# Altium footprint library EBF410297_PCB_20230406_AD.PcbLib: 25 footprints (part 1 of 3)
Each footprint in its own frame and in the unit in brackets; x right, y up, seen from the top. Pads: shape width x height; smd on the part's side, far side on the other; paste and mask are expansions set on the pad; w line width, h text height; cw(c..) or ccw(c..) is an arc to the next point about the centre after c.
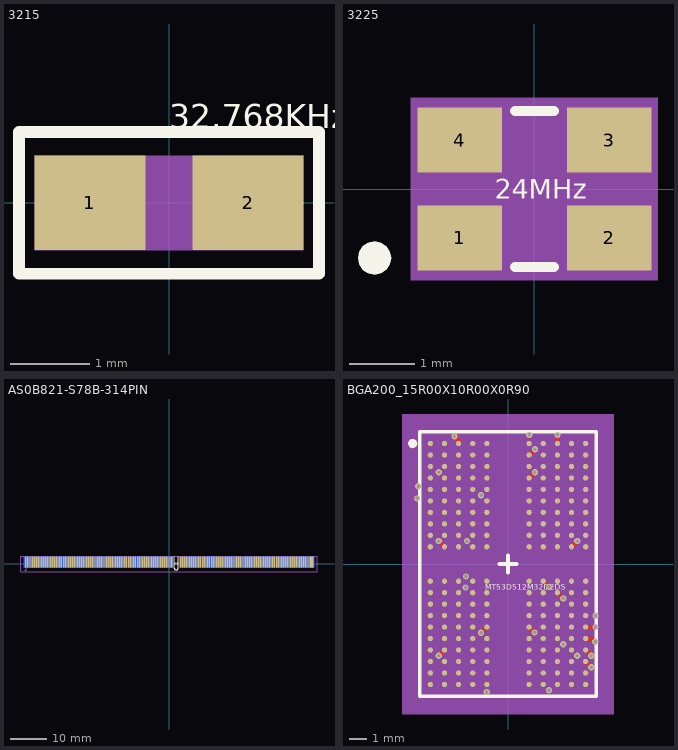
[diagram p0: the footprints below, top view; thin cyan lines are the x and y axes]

## 3215 [mm] "3215"
pads (2):
  rect 1.4x1.2 smd: 1(-1.001,0) 2(1.001,0)
Top Overlay:
  lines w0.15: -1.9,-0.899 1.9,-0.899 1.9,0.899 -1.9,0.899 -1.9,-0.899
  text "32.768KHz" at 0,0.945 h0.3
Top 3D Body:
  region: -1.699,-0.599 1.699,-0.599 1.699,0.599 -1.699,0.599
Mechanical 14:
  text "2" at 1.001,0.152 h0.38
  text "1" at -1.001,0.152 h0.38
3D body: height 3.81, standoff 0, extent -1.699,-0.599 1.699,0.599

## 3225 [mm] "3225"
pads (4):
  rect 1.3x1 smd: 1(-1.15,-0.75) 2(1.15,-0.75) 3(1.15,0.75) 4(-1.15,0.75)
Top Overlay:
  dashed: -2.201,-1.06 -2.221,-0.962 -2.276,-0.879 -2.359,-0.824 -2.456,-0.805 -2.554,-0.824 -2.581,-0.843 -2.636,-0.879 -2.692,-0.962 -2.711,-1.06 -2.692,-1.157 -2.636,-1.24 -2.581,-1.277 -2.554,-1.295 -2.456,-1.315 -2.359,-1.295 -2.276,-1.24 -2.221,-1.157
  lines w0.15: -0.3,-1.2 0.3,-1.2 ; -0.3,1.2 0.3,1.2
  text "24MHz" at -0.61,-0.152 h0.3
Top 3D Body:
  region: -1.9,1.4 -1.9,-1.4 1.9,-1.4 1.9,1.4
Mechanical 14:
  text "3" at 0.785,0.75 h0.91
  text "1" at -1.516,-0.75 h0.91
  text "4" at -1.516,0.75 h0.91
  text "2" at 0.785,-0.75 h0.91
Top Assembly:
  lines w0.15: -1.6,-1.25 -1.6,1.25 1.6,1.25 1.6,-1.25 -1.6,-1.25
3D body: height 3.81, standoff 0, extent -1.9,-1.4 1.9,1.4

## AS0B821-S78B-314PIN [mm] "AS0B821-S78B-314PIN"
pads (314):
  rect 0.35x3.1 smd far side: 1(-40,0.525) 3(-39.5,0.525) 5(-39,0.525) 7(-38.5,0.525) 9(-38,0.525) 11(-37.5,0.525) 13(-37,0.525) 15(-36.5,0.525) 17(-36,0.525) 19(-35.5,0.525) 21(-35,0.525) 23(-34.5,0.525) 25(-34,0.525) 27(-33.5,0.525) 29(-33,0.525) 31(-32.5,0.525) 33(-32,0.525) 35(-31.5,0.525) 37(-31,0.525) 39(-30.5,0.525) 41(-30,0.525) 43(-29.5,0.525) 45(-29,0.525) 47(-28.5,0.525) 49(-28,0.525) 51(-27.5,0.525) 53(-27,0.525) 55(-26.5,0.525) 57(-26,0.525) 59(-25.5,0.525) 61(-25,0.525) 63(-24.5,0.525) 65(-24,0.525) 67(-23.5,0.525) 69(-23,0.525) 71(-22.5,0.525) 73(-22,0.525) 75(-21.5,0.525) 77(-21,0.525) 79(-20.5,0.525) 81(-20,0.525) 83(-19.5,0.525) 85(-19,0.525) 87(-18.5,0.525) 89(-18,0.525) 91(-17.5,0.525) 93(-17,0.525) 95(-16.5,0.525) 97(-16,0.525) 99(-15.5,0.525) 101(-15,0.525) 103(-14.5,0.525) 105(-14,0.525) 107(-13.5,0.525) 109(-13,0.525) 111(-12.5,0.525) 113(-12,0.525) 115(-11.5,0.525) 117(-11,0.525) 119(-10.5,0.525) 121(-10,0.525) 123(-9.5,0.525) 125(-9,0.525) 127(-8.5,0.525) 129(-8,0.525) 131(-7.5,0.525) 133(-7,0.525) 135(-6.5,0.525) 137(-6,0.525) 139(-5.5,0.525) 141(-5,0.525) 143(-4.5,0.525) 145(-4,0.525) 147(-3.5,0.525) 149(-3,0.525) 151(-2.5,0.525) 153(-2,0.525) 155(-1.5,0.525) 157(-1,0.525) 159(-0.5,0.525) 161(0,0.525) 163(0.5,0.525) 165(1,0.525) 167(3,0.525) 169(3.5,0.525) 171(4,0.525) 173(4.5,0.525) 175(5,0.525) 177(5.5,0.525) 179(6,0.525) 181(6.5,0.525) 183(7,0.525) 185(7.5,0.525) 187(8,0.525) 189(8.5,0.525) 191(9,0.525) 193(9.5,0.525) 195(10,0.525) 197(10.5,0.525) 199(11,0.525) 201(11.5,0.525) 203(12,0.525) 205(12.5,0.525) 207(13,0.525) 209(13.5,0.525) 211(14,0.525) 213(14.5,0.525) 215(15,0.525) 217(15.5,0.525) 219(16,0.525) 221(16.5,0.525) 223(17,0.525) 225(17.5,0.525) 227(18,0.525) 229(18.5,0.525) 231(19,0.525) 233(19.5,0.525) 235(20,0.525) 237(20.5,0.525) 239(21,0.525) 241(21.5,0.525) 243(22,0.525) 245(22.5,0.525) 247(23,0.525) 249(23.5,0.525) 251(24,0.525) 253(24.5,0.525) 255(25,0.525) 257(25.5,0.525) 259(26,0.525) 261(26.5,0.525) 263(27,0.525) 265(27.5,0.525) 267(28,0.525) 269(28.5,0.525) 271(29,0.525) 273(29.5,0.525) 275(30,0.525) 277(30.5,0.525) 279(31,0.525) 281(31.5,0.525) 283(32,0.525) 285(32.5,0.525) 287(33,0.525) 289(33.5,0.525) 291(34,0.525) 293(34.5,0.525) 295(35,0.525) 297(35.5,0.525) 299(36,0.525) 301(36.5,0.525) 303(37,0.525) 305(37.5,0.525) 307(38,0.525) 309(38.5,0.525) 311(39,0.525) 313(39.5,0.525) 314(40,0.525)
  rect 0.35x3.1 smd: 2(-39.75,0.525) 4(-39.25,0.525) 6(-38.75,0.525) 8(-38.25,0.525) 10(-37.75,0.525) 12(-37.25,0.525) 14(-36.75,0.525) 16(-36.25,0.525) 18(-35.75,0.525) 20(-35.25,0.525) 22(-34.75,0.525) 24(-34.25,0.525) 26(-33.75,0.525) 28(-33.25,0.525) 30(-32.75,0.525) 32(-32.25,0.525) 34(-31.75,0.525) 36(-31.25,0.525) 38(-30.75,0.525) 40(-30.25,0.525) 42(-29.75,0.525) 44(-29.25,0.525) 46(-28.75,0.525) 48(-28.25,0.525) 50(-27.75,0.525) 52(-27.25,0.525) 54(-26.75,0.525) 56(-26.25,0.525) 58(-25.75,0.525) 60(-25.25,0.525) 62(-24.75,0.525) 64(-24.25,0.525) 66(-23.75,0.525) 68(-23.25,0.525) 70(-22.75,0.525) 72(-22.25,0.525) 74(-21.75,0.525) 76(-21.25,0.525) 78(-20.75,0.525) 80(-20.25,0.525) 82(-19.75,0.525) 84(-19.25,0.525) 86(-18.75,0.525) 88(-18.25,0.525) 90(-17.75,0.525) 92(-17.25,0.525) 94(-16.75,0.525) 96(-16.25,0.525) 98(-15.75,0.525) 100(-15.25,0.525) 102(-14.75,0.525) 104(-14.25,0.525) 106(-13.75,0.525) 108(-13.25,0.525) 110(-12.75,0.525) 112(-12.25,0.525) 114(-11.75,0.525) 116(-11.25,0.525) 118(-10.75,0.525) 120(-10.25,0.525) 122(-9.75,0.525) 124(-9.25,0.525) 126(-8.75,0.525) 128(-8.25,0.525) 130(-7.75,0.525) 132(-7.25,0.525) 134(-6.75,0.525) 136(-6.25,0.525) 138(-5.75,0.525) 140(-5.25,0.525) 142(-4.75,0.525) 144(-4.25,0.525) 146(-3.75,0.525) 148(-3.25,0.525) 150(-2.75,0.525) 152(-2.25,0.525) 154(-1.75,0.525) 156(-1.25,0.525) 158(-0.75,0.525) 160(-0.25,0.525) 162(0.25,0.525) 164(0.75,0.525) 166(3.25,0.525) 168(3.75,0.525) 170(4.25,0.525) 172(4.75,0.525) 174(5.25,0.525) 176(5.75,0.525) 178(6.25,0.525) 180(6.75,0.525) 182(7.25,0.525) 184(7.75,0.525) 186(8.25,0.525) 188(8.75,0.525) 190(9.25,0.525) 192(9.75,0.525) 194(10.25,0.525) 196(10.75,0.525) 198(11.25,0.525) 200(11.75,0.525) 202(12.25,0.525) 204(12.75,0.525) 206(13.25,0.525) 208(13.75,0.525) 210(14.25,0.525) 212(14.75,0.525) 214(15.25,0.525) 216(15.75,0.525) 218(16.25,0.525) 220(16.75,0.525) 222(17.25,0.525) 224(17.75,0.525) 226(18.25,0.525) 228(18.75,0.525) 230(19.25,0.525) 232(19.75,0.525) 234(20.25,0.525) 236(20.75,0.525) 238(21.25,0.525) 240(21.75,0.525) 242(22.25,0.525) 244(22.75,0.525) 246(23.25,0.525) 248(23.75,0.525) 250(24.25,0.525) 252(24.75,0.525) 254(25.25,0.525) 256(25.75,0.525) 258(26.25,0.525) 260(26.75,0.525) 262(27.25,0.525) 264(27.75,0.525) 266(28.25,0.525) 268(28.75,0.525) 270(29.25,0.525) 272(29.75,0.525) 274(30.25,0.525) 276(30.75,0.525) 278(31.25,0.525) 280(31.75,0.525) 282(32.25,0.525) 284(32.75,0.525) 286(33.25,0.525) 288(33.75,0.525) 290(34.25,0.525) 292(34.75,0.525) 294(35.25,0.525) 296(35.75,0.525) 298(36.25,0.525) 300(36.75,0.525) 302(37.25,0.525) 304(37.75,0.525) 306(38.25,0.525) 308(38.75,0.525) 310(39.25,0.525)
  rect 0.425x3.1 smd: 312(39.75,0.525)
Top Overlay:
  lines w0.15: 1.5,2.075 1.5,-1.175 ccw(c2,-1.175) 2.5,-1.175 2.5,2.075
  text "2" at -40,-1.875 h0.76
  text "AS0B821-S55B-314PIN" at -2.316,-0.152 h0.3
Bottom Overlay:
  text "1" at -39.686,-1.915 h0.76
Top 3D Body:
  lines w0.025: -41.075,-2.15 -41.075,2.15 41.075,2.15 41.075,-2.15 -41.075,-2.15
Mechanical 14:
  text "102" at -15.512,0.525 h0.64
  text "104" at -15.012,0.525 h0.64
  text "193" at 8.738,0.525 h0.64
  text "191" at 8.238,0.525 h0.64
  text "232" at 18.988,0.525 h0.64
  text "161" at -0.762,0.525 h0.64
  text "230" at 18.488,0.525 h0.64
  text "163" at -0.262,0.525 h0.64
  text "236" at 19.988,0.525 h0.64
  text "234" at 19.488,0.525 h0.64
  text "118" at -11.512,0.525 h0.64
  text "165" at 0.238,0.525 h0.64
  text "252" at 23.988,0.525 h0.64
  text "71" at -23.008,0.525 h0.64
  text "250" at 23.488,0.525 h0.64
  text "73" at -22.508,0.525 h0.64
  text "256" at 24.988,0.525 h0.64
  text "69" at -23.508,0.525 h0.64
  text "120" at -11.012,0.525 h0.64
  text "254" at 24.488,0.525 h0.64
  text "61" at -25.508,0.525 h0.64
  text "242" at 21.488,0.525 h0.64
  text "240" at 20.988,0.525 h0.64
  text "124" at -10.012,0.525 h0.64
  text "246" at 22.488,0.525 h0.64
  text "126" at -9.512,0.525 h0.64
  text "244" at 21.988,0.525 h0.64
  text "63" at -25.008,0.525 h0.64
  text "305" at 36.738,0.525 h0.64
  text "307" at 37.238,0.525 h0.64
  text "303" at 36.238,0.525 h0.64
  text "65" at -24.508,0.525 h0.64
  text "301" at 35.738,0.525 h0.64
  text "29" at -33.508,0.525 h0.64
  text "66" at -24.258,0.525 h0.64
  text "64" at -24.758,0.525 h0.64
  text "199" at 10.238,0.525 h0.64
  text "197" at 9.738,0.525 h0.64
  text "267" at 27.238,0.525 h0.64
  text "203" at 11.238,0.525 h0.64
  text "265" at 26.738,0.525 h0.64
  text "201" at 10.738,0.525 h0.64
  text "313" at 38.738,0.525 h0.64
  text "215" at 14.238,0.525 h0.64
  text "213" at 13.738,0.525 h0.64
  text "219" at 15.238,0.525 h0.64
  text "314" at 39.238,0.525 h0.64
  text "217" at 14.738,0.525 h0.64
  text "209" at 12.738,0.525 h0.64
  text "6" at -39.004,0.525 h0.64
  text "2" at -40.004,0.525 h0.64
  text "4" at -39.504,0.525 h0.64
  text "5" at -39.254,0.525 h0.64
  text "3" at -39.754,0.525 h0.64
  text "1" at -40.254,0.525 h0.64
  text "207" at 12.238,0.525 h0.64
  text "269" at 27.738,0.525 h0.64
  text "266" at 27.488,0.525 h0.64
  text "114" at -12.512,0.525 h0.64
  text "270" at 28.488,0.525 h0.64
  text "59" at -26.008,0.525 h0.64
  text "112" at -13.012,0.525 h0.64
  text "271" at 28.238,0.525 h0.64
  text "262" at 26.488,0.525 h0.64
  text "57" at -26.508,0.525 h0.64
  text "110" at -13.512,0.525 h0.64
  text "264" at 26.988,0.525 h0.64
  text "55" at -27.008,0.525 h0.64
  text "108" at -14.012,0.525 h0.64
  text "268" at 27.988,0.525 h0.64
  text "75" at -22.008,0.525 h0.64
  text "129" at -8.762,0.525 h0.64
  text "260" at 25.988,0.525 h0.64
  text "79" at -21.008,0.525 h0.64
  text "136" at -7.012,0.525 h0.64
  text "77" at -21.508,0.525 h0.64
  text "134" at -7.512,0.525 h0.64
  text "132" at -8.012,0.525 h0.64
  text "130" at -8.512,0.525 h0.64
  text "89" at -18.508,0.525 h0.64
  text "83" at -20.008,0.525 h0.64
  text "142" at -5.512,0.525 h0.64
  text "140" at -6.012,0.525 h0.64
  text "85" at -19.508,0.525 h0.64
  text "70" at -23.258,0.525 h0.64
  text "68" at -23.758,0.525 h0.64
  text "275" at 29.238,0.525 h0.64
  text "273" at 28.738,0.525 h0.64
  text "284" at 31.988,0.525 h0.64
  text "282" at 31.488,0.525 h0.64
  text "277" at 29.738,0.525 h0.64
  text "274" at 29.488,0.525 h0.64
  text "279" at 30.238,0.525 h0.64
  text "178" at 5.488,0.525 h0.64
  text "287" at 32.238,0.525 h0.64
  text "291" at 33.238,0.525 h0.64
  text "289" at 32.738,0.525 h0.64
  text "180" at 5.988,0.525 h0.64
  text "182" at 6.488,0.525 h0.64
  text "74" at -22.258,0.525 h0.64
  text "76" at -21.758,0.525 h0.64
  text "78" at -21.258,0.525 h0.64
  text "302" at 36.488,0.525 h0.64
  text "80" at -20.758,0.525 h0.64
  text "304" at 36.988,0.525 h0.64
  text "99" at -16.008,0.525 h0.64
  text "82" at -20.258,0.525 h0.64
  text "105" at -14.762,0.525 h0.64
  text "84" at -19.758,0.525 h0.64
  text "93" at -17.508,0.525 h0.64
  text "86" at -19.258,0.525 h0.64
  text "296" at 34.988,0.525 h0.64
  text "103" at -15.262,0.525 h0.64
  text "88" at -18.758,0.525 h0.64
  text "298" at 35.488,0.525 h0.64
  text "97" at -16.508,0.525 h0.64
  text "35" at -32.008,0.525 h0.64
  text "95" at -17.008,0.525 h0.64
  text "37" at -31.508,0.525 h0.64
  text "13" at -37.508,0.525 h0.64
  text "15" at -37.008,0.525 h0.64
  text "92" at -17.758,0.525 h0.64
  text "94" at -17.258,0.525 h0.64
  text "276" at 29.988,0.525 h0.64
  text "278" at 30.488,0.525 h0.64
  text "280" at 30.988,0.525 h0.64
  text "293" at 33.738,0.525 h0.64
  text "297" at 34.738,0.525 h0.64
  text "295" at 34.238,0.525 h0.64
  text "308" at 37.988,0.525 h0.64
  text "115" at -12.262,0.525 h0.64
  text "113" at -12.762,0.525 h0.64
  text "310" at 38.488,0.525 h0.64
  text "36" at -31.758,0.525 h0.64
  text "34" at -32.258,0.525 h0.64
  text "292" at 33.988,0.525 h0.64
  text "290" at 33.488,0.525 h0.64
  text "211" at 13.238,0.525 h0.64
  text "249" at 22.738,0.525 h0.64
  text "311" at 38.238,0.525 h0.64
  text "294" at 34.488,0.525 h0.64
  text "272" at 28.988,0.525 h0.64
  text "312" at 38.988,0.525 h0.64
  text "300" at 35.988,0.525 h0.64
  text "285" at 31.738,0.525 h0.64
  text "288" at 32.988,0.525 h0.64
  text "263" at 26.238,0.525 h0.64
  text "258" at 25.488,0.525 h0.64
  text "221" at 15.738,0.525 h0.64
  text "229" at 17.738,0.525 h0.64
  text "194" at 9.488,0.525 h0.64
  text "7" at -38.754,0.525 h0.64
  text "8" at -38.504,0.525 h0.64
  text "9" at -38.254,0.525 h0.64
  text "11" at -38.008,0.525 h0.64
  text "10" at -38.258,0.525 h0.64
  text "12" at -37.758,0.525 h0.64
  text "39" at -31.008,0.525 h0.64
  text "53" at -27.508,0.525 h0.64
  text "67" at -24.008,0.525 h0.64
  text "87" at -19.008,0.525 h0.64
  text "167" at 2.238,0.525 h0.64
  text "166" at 2.488,0.525 h0.64
  text "32" at -32.758,0.525 h0.64
  text "38" at -31.258,0.525 h0.64
  text "46" at -29.258,0.525 h0.64
  text "72" at -22.758,0.525 h0.64
  text "90" at -18.258,0.525 h0.64
  text "96" at -16.758,0.525 h0.64
  text "100" at -16.012,0.525 h0.64
  text "106" at -14.512,0.525 h0.64
  text "116" at -12.012,0.525 h0.64
  text "122" at -10.512,0.525 h0.64
  text "164" at -0.012,0.525 h0.64
  text "25" at -34.508,0.525 h0.64
  text "24" at -34.758,0.525 h0.64
  text "27" at -34.008,0.525 h0.64
  text "26" at -34.258,0.525 h0.64
  text "62" at -25.258,0.525 h0.64
  text "81" at -20.508,0.525 h0.64
  text "91" at -18.008,0.525 h0.64
  text "128" at -9.012,0.525 h0.64
  text "107" at -14.262,0.525 h0.64
  text "117" at -11.762,0.525 h0.64
  text "204" at 11.988,0.525 h0.64
  text "195" at 9.238,0.525 h0.64
  text "205" at 11.738,0.525 h0.64
  text "138" at -6.512,0.525 h0.64
  text "144" at -5.012,0.525 h0.64
  text "141" at -5.762,0.525 h0.64
  text "154" at -2.512,0.525 h0.64
  text "176" at 4.988,0.525 h0.64
  text "135" at -7.262,0.525 h0.64
  text "159" at -1.262,0.525 h0.64
  text "22" at -35.258,0.525 h0.64
  text "18" at -36.258,0.525 h0.64
  text "228" at 17.988,0.525 h0.64
  text "238" at 20.488,0.525 h0.64
  text "214" at 14.488,0.525 h0.64
  text "239" at 20.238,0.525 h0.64
  text "299" at 35.238,0.525 h0.64
  text "306" at 37.488,0.525 h0.64
  text "248" at 22.988,0.525 h0.64
  text "14" at -37.258,0.525 h0.64
  text "16" at -36.758,0.525 h0.64
  text "143" at -5.262,0.525 h0.64
  text "145" at -4.762,0.525 h0.64
  text "286" at 32.488,0.525 h0.64
  text "58" at -26.258,0.525 h0.64
  text "17" at -36.508,0.525 h0.64
  text "19" at -36.008,0.525 h0.64
  text "52" at -27.758,0.525 h0.64
  text "54" at -27.258,0.525 h0.64
  text "48" at -28.758,0.525 h0.64
  text "147" at -4.262,0.525 h0.64
  text "50" at -28.258,0.525 h0.64
  text "149" at -3.762,0.525 h0.64
  text "23" at -35.008,0.525 h0.64
  text "21" at -35.508,0.525 h0.64
  text "30" at -33.258,0.525 h0.64
  text "28" at -33.758,0.525 h0.64
  text "151" at -3.262,0.525 h0.64
  text "153" at -2.762,0.525 h0.64
  text "155" at -2.262,0.525 h0.64
  text "157" at -1.762,0.525 h0.64
  text "137" at -6.762,0.525 h0.64
  text "139" at -6.262,0.525 h0.64
  text "40" at -30.758,0.525 h0.64
  text "44" at -29.758,0.525 h0.64
  text "42" at -30.258,0.525 h0.64
  text "186" at 7.488,0.525 h0.64
  text "188" at 7.988,0.525 h0.64
  text "190" at 8.488,0.525 h0.64
  text "192" at 8.988,0.525 h0.64
  text "196" at 9.988,0.525 h0.64
  text "198" at 10.488,0.525 h0.64
  text "200" at 10.988,0.525 h0.64
  text "202" at 11.488,0.525 h0.64
  text "184" at 6.988,0.525 h0.64
  text "127" at -9.262,0.525 h0.64
  text "133" at -7.762,0.525 h0.64
  text "125" at -9.762,0.525 h0.64
  text "131" at -8.262,0.525 h0.64
  text "119" at -11.262,0.525 h0.64
  text "158" at -1.512,0.525 h0.64
  text "60" at -25.758,0.525 h0.64
  text "101" at -15.762,0.525 h0.64
  text "172" at 3.988,0.525 h0.64
  text "174" at 4.488,0.525 h0.64
  text "183" at 6.238,0.525 h0.64
  text "152" at -3.012,0.525 h0.64
  text "148" at -4.012,0.525 h0.64
  text "146" at -4.512,0.525 h0.64
  text "150" at -3.512,0.525 h0.64
  text "51" at -28.008,0.525 h0.64
  text "45" at -29.508,0.525 h0.64
  text "47" at -29.008,0.525 h0.64
  text "43" at -30.008,0.525 h0.64
  text "49" at -28.508,0.525 h0.64
  text "41" at -30.508,0.525 h0.64
  text "111" at -13.262,0.525 h0.64
  text "109" at -13.762,0.525 h0.64
  text "281" at 30.738,0.525 h0.64
  text "33" at -32.508,0.525 h0.64
  text "283" at 31.238,0.525 h0.64
  text "31" at -33.008,0.525 h0.64
  text "309" at 37.738,0.525 h0.64
  text "171" at 3.238,0.525 h0.64
  text "169" at 2.738,0.525 h0.64
  text "175" at 4.238,0.525 h0.64
  text "20" at -35.758,0.525 h0.64
  text "179" at 5.238,0.525 h0.64
  text "121" at -10.762,0.525 h0.64
  text "181" at 5.738,0.525 h0.64
  text "177" at 4.738,0.525 h0.64
  text "56" at -26.758,0.525 h0.64
  text "231" at 18.238,0.525 h0.64
  text "227" at 17.238,0.525 h0.64
  text "225" at 16.738,0.525 h0.64
  text "223" at 16.238,0.525 h0.64
  text "233" at 18.738,0.525 h0.64
  text "162" at -0.512,0.525 h0.64
  text "160" at -1.012,0.525 h0.64
  text "253" at 23.738,0.525 h0.64
  text "261" at 25.738,0.525 h0.64
  text "237" at 19.738,0.525 h0.64
  text "255" at 24.238,0.525 h0.64
  text "259" at 25.238,0.525 h0.64
  text "212" at 13.988,0.525 h0.64
  text "243" at 21.238,0.525 h0.64
  text "208" at 12.988,0.525 h0.64
  text "245" at 21.738,0.525 h0.64
  text "210" at 13.488,0.525 h0.64
  text "247" at 22.238,0.525 h0.64
  text "206" at 12.488,0.525 h0.64
  text "235" at 19.238,0.525 h0.64
  text "251" at 23.238,0.525 h0.64
  text "216" at 14.988,0.525 h0.64
  text "218" at 15.488,0.525 h0.64
  text "257" at 24.738,0.525 h0.64
  text "168" at 2.988,0.525 h0.64
  text "226" at 17.488,0.525 h0.64
  text "222" at 16.488,0.525 h0.64
  text "220" at 15.988,0.525 h0.64
  text "185" at 6.738,0.525 h0.64
  text "187" at 7.238,0.525 h0.64
  text "123" at -10.262,0.525 h0.64
  text "173" at 3.738,0.525 h0.64
  text "170" at 3.488,0.525 h0.64
  text "241" at 20.738,0.525 h0.64
  text "224" at 16.988,0.525 h0.64
  text "189" at 7.738,0.525 h0.64
  text "156" at -2.012,0.525 h0.64
  text "98" at -16.258,0.525 h0.64

## BGA200_15R00X10R00X0R90 [mm] "BGA200_15R00X10R00X0R90"
pads (200):
  round 0.3 smd: A1(-4.4,6.825) A2(-3.6,6.825) A3(-2.8,6.825) A4(-2,6.825) A5(-1.2,6.825) A8(1.2,6.825) A9(2,6.825) A10(2.8,6.825) A11(3.6,6.825) A12(4.4,6.825) AA1(-4.4,-6.175) AA2(-3.6,-6.175) AA3(-2.8,-6.175) AA4(-2,-6.175) AA5(-1.2,-6.175) AA8(1.2,-6.175) AA9(2,-6.175) AA10(2.8,-6.175) AA11(3.6,-6.175) AA12(4.4,-6.175) AB1(-4.4,-6.825) AB2(-3.6,-6.825) AB3(-2.8,-6.825) AB4(-2,-6.825) AB5(-1.2,-6.825) AB8(1.2,-6.825) AB9(2,-6.825) AB10(2.8,-6.825) AB11(3.6,-6.825) AB12(4.4,-6.825) B1(-4.4,6.175) B2(-3.6,6.175) B3(-2.8,6.175) B4(-2,6.175) B5(-1.2,6.175) B8(1.2,6.175) B9(2,6.175) B10(2.8,6.175) B11(3.6,6.175) B12(4.4,6.175) C1(-4.4,5.525) C2(-3.6,5.525) C3(-2.8,5.525) C4(-2,5.525) C5(-1.2,5.525) C8(1.2,5.525) C9(2,5.525) C10(2.8,5.525) C11(3.6,5.525) C12(4.4,5.525) D1(-4.4,4.875) D2(-3.6,4.875) D3(-2.8,4.875) D4(-2,4.875) D5(-1.2,4.875) D8(1.2,4.875) D9(2,4.875) D10(2.8,4.875) D11(3.6,4.875) D12(4.4,4.875) E1(-4.4,4.225) E2(-3.6,4.225) E3(-2.8,4.225) E4(-2,4.225) E5(-1.2,4.225) E8(1.2,4.225) E9(2,4.225) E10(2.8,4.225) E11(3.6,4.225) E12(4.4,4.225) F1(-4.4,3.575) F2(-3.6,3.575) F3(-2.8,3.575) F4(-2,3.575) F5(-1.2,3.575) F8(1.2,3.575) F9(2,3.575) F10(2.8,3.575) F11(3.6,3.575) F12(4.4,3.575) G1(-4.4,2.925) G2(-3.6,2.925) G3(-2.8,2.925) G4(-2,2.925) G5(-1.2,2.925) G8(1.2,2.925) G9(2,2.925) G10(2.8,2.925) G11(3.6,2.925) G12(4.4,2.925) H1(-4.4,2.275) H2(-3.6,2.275) H3(-2.8,2.275) H4(-2,2.275) H5(-1.2,2.275) H8(1.2,2.275) H9(2,2.275) H10(2.8,2.275) H11(3.6,2.275) H12(4.4,2.275) J1(-4.4,1.625) J2(-3.6,1.625) J3(-2.8,1.625) J4(-2,1.625) J5(-1.2,1.625) J8(1.2,1.625) J9(2,1.625) J10(2.8,1.625) J11(3.6,1.625) J12(4.4,1.625) K1(-4.4,0.975) K2(-3.6,0.975) K3(-2.8,0.975) K4(-2,0.975) K5(-1.2,0.975) K8(1.2,0.975) K9(2,0.975) K10(2.8,0.975) K11(3.6,0.975) K12(4.4,0.975) N1(-4.4,-0.975) N2(-3.6,-0.975) N3(-2.8,-0.975) N4(-2,-0.975) N5(-1.2,-0.975) N8(1.2,-0.975) N9(2,-0.975) N10(2.8,-0.975) N11(3.6,-0.975) N12(4.4,-0.975) P1(-4.4,-1.625) P2(-3.6,-1.625) P3(-2.8,-1.625) P4(-2,-1.625) P5(-1.2,-1.625) P8(1.2,-1.625) P9(2,-1.625) P10(2.8,-1.625) P11(3.6,-1.625) P12(4.4,-1.625) R1(-4.4,-2.275) R2(-3.6,-2.275) R3(-2.8,-2.275) R4(-2,-2.275) R5(-1.2,-2.275) R8(1.2,-2.275) R9(2,-2.275) R10(2.8,-2.275) R11(3.6,-2.275) R12(4.4,-2.275) T1(-4.4,-2.925) T2(-3.6,-2.925) T3(-2.8,-2.925) T4(-2,-2.925) T5(-1.2,-2.925) T8(1.2,-2.925) T9(2,-2.925) T10(2.8,-2.925) T11(3.6,-2.925) T12(4.4,-2.925) U1(-4.4,-3.575) U2(-3.6,-3.575) U3(-2.8,-3.575) U4(-2,-3.575) U5(-1.2,-3.575) U8(1.2,-3.575) U9(2,-3.575) U10(2.8,-3.575) U11(3.6,-3.575) U12(4.4,-3.575) V1(-4.4,-4.225) V2(-3.6,-4.225) V3(-2.8,-4.225) V4(-2,-4.225) V5(-1.2,-4.225) V8(1.2,-4.225) V9(2,-4.225) V10(2.8,-4.225) V11(3.6,-4.225) V12(4.4,-4.225) W1(-4.4,-4.875) W2(-3.6,-4.875) W3(-2.8,-4.875) W4(-2,-4.875) W5(-1.2,-4.875) W8(1.2,-4.875) W9(2,-4.875) W10(2.8,-4.875) W11(3.6,-4.875) W12(4.4,-4.875) Y1(-4.4,-5.525) Y2(-3.6,-5.525) Y3(-2.8,-5.525) Y4(-2,-5.525) Y5(-1.2,-5.525) Y8(1.2,-5.525) Y9(2,-5.525) Y10(2.8,-5.525) Y11(3.6,-5.525) Y12(4.4,-5.525)
via 2.8,7.313 diameter 0.356 hole 0.203
via 1.2,7.313 diameter 0.356 hole 0.203
via 1.525,6.5 diameter 0.356 hole 0.203
via 1.525,5.2 diameter 0.356 hole 0.203
via 3.925,1.3 diameter 0.356 hole 0.203
via -3.035,7.24 diameter 0.356 hole 0.203
via -1.525,3.9 diameter 0.356 hole 0.203
via 4.954,-2.928 diameter 0.356 hole 0.203
via 4.953,-3.575 diameter 0.356 hole 0.203
via -3.925,5.2 diameter 0.356 hole 0.203
via 3.125,-1.95 diameter 0.356 hole 0.203
via 2.325,-1.3 diameter 0.356 hole 0.203
via 4.95,-4.404 diameter 0.356 hole 0.203
via 4.725,-5.2 diameter 0.356 hole 0.203
via -5.079,4.411 diameter 0.356 hole 0.203
via -2.325,1.3 diameter 0.356 hole 0.203
via 4.725,-5.85 diameter 0.356 hole 0.203
via 3.925,-5.2 diameter 0.356 hole 0.203
via 3.125,-4.55 diameter 0.356 hole 0.203
via -5.158,3.714 diameter 0.356 hole 0.203
via 1.503,-3.879 diameter 0.356 hole 0.203
via -3.925,1.3 diameter 0.356 hole 0.203
via -2.382,-0.708 diameter 0.356 hole 0.203
via -2.403,-1.333 diameter 0.356 hole 0.203
via 2.325,-7.15 diameter 0.356 hole 0.203
via -1.525,-3.9 diameter 0.356 hole 0.203
via -1.2,-7.254 diameter 0.356 hole 0.203
via -3.925,-5.2 diameter 0.356 hole 0.203
Top Layer:
  lines w0.102: 1.2,6.825 1.2,7.313
  lines w0.254: -3.925,-5.2 -3.6,-4.875 ; -3.925,1.3 -3.6,0.975 ; -3.035,7.24 -2.8,7.005 -2.8,6.825 ; -1.525,-3.9 -1.2,-3.575 ; 1.2,-3.575 1.503,-3.879 ; 1.2,4.875 1.525,5.2 ; 1.2,6.175 1.525,6.5 ; 2,-0.975 2.325,-1.3 ; 2.8,-1.625 3.125,-1.95 ; 2.8,6.825 2.8,7.313 ; 3.6,0.975 3.925,1.3 ; 4.4,-5.525 4.725,-5.85 ; 4.4,-4.225 4.771,-4.225 4.95,-4.404 ; 4.4,-3.575 4.953,-3.575 ; 4.725,-5.2 4.4,-4.875 ; 4.4,-4.875 4.4,-4.875
Top Overlay:
  dashed: -5.22,7.005 -5.302,7.06 -5.4,7.08 -5.498,7.06 -5.58,7.005 -5.635,6.923 -5.642,6.89 -5.655,6.825 -5.635,6.727 -5.58,6.645 -5.498,6.59 -5.4,6.57 -5.335,6.583 -5.302,6.59 -5.22,6.645 -5.165,6.727 -5.145,6.825 -5.165,6.923
  lines w0.2: -0.5,0 0,0 ; 0,-0.5 0,0 ; 0,0.5 0,0 ; 0.5,0 0,0 ; -5,-7.5 -5,7.5 5,7.5 5,-7.5 -5,-7.5
  text "MT53D512M32D2DS" at -1.294,-1.445 h0.3
Top 3D Body:
  region: -6,-8.5 -6,8.5 6,8.5 6,-8.5
Mechanical 14:
  text "K8" at 0.97,0.745 h0.41
  text "N8" at 0.97,-1.205 h0.41
  text "K5" at -1.43,0.745 h0.41
  text "N5" at -1.43,-1.205 h0.41
  text "G11" at 3.255,2.58 h0.41
  text "A1" at -4.63,6.595 h0.41
  text "AB2" at -3.945,-7.17 h0.41
  text "AB11" at 3.14,-7.285 h0.41
  text "AB12" at 3.94,-7.285 h0.41
  text "A2" at -3.83,6.595 h0.41
  text "A11" at 3.255,6.48 h0.41
  text "A12" at 4.055,6.48 h0.41
  text "B1" at -4.63,5.945 h0.41
  text "B12" at 4.055,5.83 h0.41
  text "AA1" at -4.745,-6.52 h0.41
  text "AA12" at 3.94,-6.635 h0.41
  text "AB1" at -4.745,-7.17 h0.41
  text "F3" at -3.03,3.345 h0.41
  text "U3" at -3.03,-3.805 h0.41
  text "D1" at -4.63,4.645 h0.41
  text "B3" at -3.03,5.945 h0.41
  text "B10" at 2.455,5.83 h0.41
  text "D12" at 4.055,4.53 h0.41
  text "F10" at 2.455,3.23 h0.41
  text "D5" at -1.43,4.645 h0.41
  text "D8" at 0.97,4.645 h0.41
  text "B8" at 0.97,5.945 h0.41
  text "B5" at -1.43,5.945 h0.41
  text "W1" at -4.63,-5.105 h0.41
  text "U10" at 2.455,-3.92 h0.41
  text "AA3" at -3.145,-6.52 h0.41
  text "W5" at -1.43,-5.105 h0.41
  text "W12" at 4.055,-5.22 h0.41
  text "AA10" at 2.34,-6.635 h0.41
  text "W8" at 0.97,-5.105 h0.41
  text "AA5" at -1.545,-6.52 h0.41
  text "AA8" at 0.855,-6.52 h0.41
  text "B2" at -3.83,5.945 h0.41
  text "C2" at -3.83,5.295 h0.41
  text "E2" at -3.83,3.995 h0.41
  text "F2" at -3.83,3.345 h0.41
  text "F4" at -2.23,3.345 h0.41
  text "E4" at -2.23,3.995 h0.41
  text "C4" at -2.23,5.295 h0.41
  text "B4" at -2.23,5.945 h0.41
  text "C3" at -3.03,5.295 h0.41
  text "D3" at -3.03,4.645 h0.41
  text "E3" at -3.03,3.995 h0.41
  text "B11" at 3.255,5.83 h0.41
  text "C11" at 3.255,5.18 h0.41
  text "E11" at 3.255,3.88 h0.41
  text "F11" at 3.255,3.23 h0.41
  text "F9" at 1.77,3.345 h0.41
  text "E9" at 1.77,3.995 h0.41
  text "C9" at 1.77,5.295 h0.41
  text "B9" at 1.77,5.945 h0.41
  text "C10" at 2.455,5.18 h0.41
  text "D10" at 2.455,4.53 h0.41
  text "E10" at 2.455,3.88 h0.41
  text "AA2" at -3.945,-6.52 h0.41
  text "Y2" at -3.83,-5.755 h0.41
  text "V2" at -3.83,-4.455 h0.41
  text "U2" at -3.83,-3.805 h0.41
  text "U4" at -2.23,-3.805 h0.41
  text "V4" at -2.23,-4.455 h0.41
  text "Y4" at -2.23,-5.755 h0.41
  text "AA4" at -2.345,-6.52 h0.41
  text "A5" at -1.43,6.595 h0.41
  text "Y3" at -3.03,-5.755 h0.41
  text "A8" at 0.97,6.595 h0.41
  text "W3" at -3.03,-5.105 h0.41
  text "V3" at -3.03,-4.455 h0.41
  text "F1" at -4.63,3.345 h0.41
  text "F12" at 4.055,3.23 h0.41
  text "G4" at -2.23,2.695 h0.41
  text "G9" at 1.77,2.695 h0.41
  text "T4" at -2.23,-3.155 h0.41
  text "T9" at 1.77,-3.155 h0.41
  text "U1" at -4.63,-3.805 h0.41
  text "U12" at 4.055,-3.92 h0.41
  text "AA11" at 3.14,-6.635 h0.41
  text "Y11" at 3.255,-5.87 h0.41
  text "V11" at 3.255,-4.57 h0.41
  text "U11" at 3.255,-3.92 h0.41
  text "U9" at 1.77,-3.805 h0.41
  text "V9" at 1.77,-4.455 h0.41
  text "Y9" at 1.77,-5.755 h0.41
  text "AA9" at 1.655,-6.52 h0.41
  text "Y10" at 2.455,-5.87 h0.41
  text "W10" at 2.455,-5.22 h0.41
  text "V10" at 2.455,-4.57 h0.41
  text "P8" at 0.97,-1.855 h0.41
  text "J2" at -3.83,1.395 h0.41
  text "J5" at -1.43,1.395 h0.41
  text "R10" at 2.455,-2.62 h0.41
  text "P11" at 3.255,-1.97 h0.41
  text "P2" at -3.83,-1.855 h0.41
  text "T2" at -3.83,-3.155 h0.41
  text "G2" at -3.83,2.695 h0.41
  text "P9" at 1.77,-1.855 h0.41
  text "P4" at -2.23,-1.855 h0.41
  text "H2" at -3.83,2.045 h0.41
  text "H10" at 2.455,1.93 h0.41
  text "R2" at -3.83,-2.505 h0.41
  text "H11" at 3.255,1.93 h0.41
  text "H9" at 1.77,2.045 h0.41
  text "P10" at 2.455,-1.97 h0.41
  text "Y5" at -1.43,-5.755 h0.41
  text "J10" at 2.455,1.28 h0.41
  text "T10" at 2.455,-3.27 h0.41
  text "N9" at 1.77,-1.205 h0.41
  text "E1" at -4.63,3.995 h0.41
  text "G1" at -4.63,2.695 h0.41
  text "J1" at -4.63,1.395 h0.41
  text "K2" at -3.83,0.745 h0.41
  text "J3" at -3.03,1.395 h0.41
  text "K4" at -2.23,0.745 h0.41
  text "G3" at -3.03,2.695 h0.41
  text "E5" at -1.43,3.995 h0.41
  text "G10" at 2.455,2.58 h0.41
  text "K9" at 1.77,0.745 h0.41
  text "A3" at -3.03,6.595 h0.41
  text "A10" at 2.455,6.48 h0.41
  text "C1" at -4.63,5.295 h0.41
  text "C5" at -1.43,5.295 h0.41
  text "C8" at 0.97,5.295 h0.41
  text "C12" at 4.055,5.18 h0.41
  text "D2" at -3.83,4.645 h0.41
  text "D4" at -2.23,4.645 h0.41
  text "D9" at 1.77,4.645 h0.41
  text "D11" at 3.255,4.53 h0.41
  text "E8" at 0.97,3.995 h0.41
  text "E12" at 4.055,3.88 h0.41
  text "G5" at -1.43,2.695 h0.41
  text "G8" at 0.97,2.695 h0.41
  text "G12" at 4.055,2.58 h0.41
  text "J12" at 4.055,1.28 h0.41
  text "K11" at 3.255,0.63 h0.41
  text "N2" at -3.83,-1.205 h0.41
  text "N4" at -2.23,-1.205 h0.41
  text "N11" at 3.255,-1.32 h0.41
  text "P1" at -4.63,-1.855 h0.41
  text "P3" at -3.03,-1.855 h0.41
  text "P12" at 4.055,-1.97 h0.41
  text "T1" at -4.63,-3.155 h0.41
  text "T3" at -3.03,-3.155 h0.41
  text "T5" at -1.43,-3.155 h0.41
  text "T8" at 0.97,-3.155 h0.41
  text "T12" at 4.055,-3.27 h0.41
  text "V1" at -4.63,-4.455 h0.41
  text "V5" at -1.43,-4.455 h0.41
  text "V8" at 0.97,-4.455 h0.41
  text "V12" at 4.055,-4.57 h0.41
  text "W2" at -3.83,-5.105 h0.41
  text "W4" at -2.23,-5.105 h0.41
  text "W9" at 1.77,-5.105 h0.41
  text "W11" at 3.255,-5.22 h0.41
  text "Y1" at -4.63,-5.755 h0.41
  text "Y8" at 0.97,-5.755 h0.41
  text "Y12" at 4.055,-5.87 h0.41
  text "AB3" at -3.145,-7.17 h0.41
  text "AB5" at -1.545,-7.17 h0.41
  text "AB8" at 0.855,-7.17 h0.41
  text "AB10" at 2.34,-7.285 h0.41
  text "J11" at 3.255,1.28 h0.41
  text "P5" at -1.43,-1.855 h0.41
  text "R9" at 1.77,-2.505 h0.41
  text "R11" at 3.255,-2.62 h0.41
  text "J4" at -2.23,1.395 h0.41
  text "J8" at 0.97,1.395 h0.41
  text "J9" at 1.77,1.395 h0.41
  text "H4" at -2.23,2.045 h0.41
  text "H3" at -3.03,2.045 h0.41
  text "R3" at -3.03,-2.505 h0.41
  text "R4" at -2.23,-2.505 h0.41
  text "T11" at 3.255,-3.27 h0.41
  text "R8" at 0.97,-2.505 h0.41
  text "A4" at -2.23,6.595 h0.41
  text "A9" at 1.77,6.595 h0.41
  text "F5" at -1.43,3.345 h0.41
  text "F8" at 0.97,3.345 h0.41
  text "H1" at -4.63,2.045 h0.41
  text "H5" at -1.43,2.045 h0.41
  text "H8" at 0.97,2.045 h0.41
  text "H12" at 4.055,1.93 h0.41
  text "K1" at -4.63,0.745 h0.41
  text "K3" at -3.03,0.745 h0.41
  text "K10" at 2.455,0.63 h0.41
  text "K12" at 4.055,0.63 h0.41
  text "N1" at -4.63,-1.205 h0.41
  text "N3" at -3.03,-1.205 h0.41
  text "N10" at 2.455,-1.32 h0.41
  text "N12" at 4.055,-1.32 h0.41
  text "R1" at -4.63,-2.505 h0.41
  text "R5" at -1.43,-2.505 h0.41
  text "R12" at 4.055,-2.62 h0.41
  text "U5" at -1.43,-3.805 h0.41
  text "U8" at 0.97,-3.805 h0.41
  text "AB4" at -2.345,-7.17 h0.41
  text "AB9" at 1.655,-7.17 h0.41
Top Assembly:
  dashed: -5.08,7.62 -5.08,-7.62 5.08,-7.62 5.08,7.62
3D body: height 3.81, standoff 0, extent -6,-8.5 6,8.5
